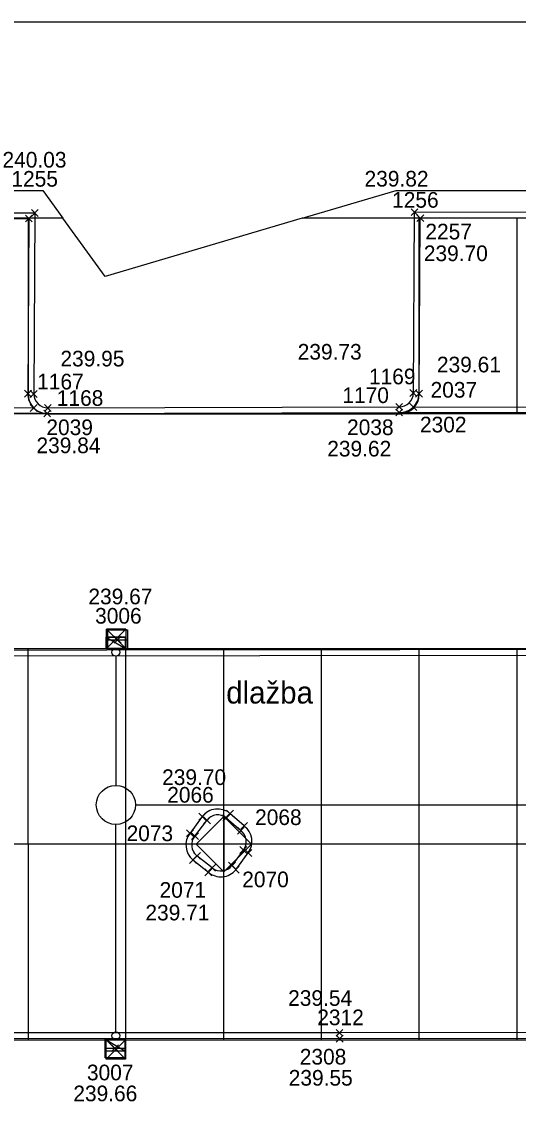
# Model space of a CAD drawing. Extents: x -264222 to -263676, y -1242344 to -1242060.
# Drawn here: x -264179.73 to -264167.04, y -1242214.48 to -1242186.47 of the extents above; entities that cross this region are included whole.
import ezdxf

# ---------------------------------------------------------------- set-up
doc = ezdxf.new("R2010")
doc.units = 0
for name, color, linetype in [('BODY_CISLO', 7, 'Continuous'), ('BODY_SYMBOL', 7, 'Continuous'), ('BODY_VYSKA', 7, 'Continuous'), ('BODY_VYSKY_UV', 7, 'Continuous'), ('KOORDINACNA_SITUACIA_DSP', 7, 'Continuous'), ('POPIS', 7, 'Continuous'), ('PROJEKT_DRS_OBRUBNIKY_KOMUNIKACIE', 7, 'Continuous'), ('PROJEKT_DRS_TDZ_VODOROVNE', 7, 'Continuous'), ('PROJEKT_DRS_UV_STAVBY', 7, 'Continuous'), ('RAM_NA_TLAC_8xA4_1-200', 7, 'Continuous'), ('SO_20-3_OBRUBNIKY_DOLNA_HRANA', 7, 'Continuous'), ('SO_20-3_OBRUBNIKY_HORNA_HRANA', 7, 'Continuous'), ('ULICNA_VPUST_POKLOP', 7, 'Continuous')]:
    doc.layers.add(name, color=color, linetype=linetype)

msp = doc.modelspace()

# ---------------------------------------------------------------- linework, layer by layer
at = {"layer": 'BODY_SYMBOL'}
for p, q in [((-264179.485, -1242191.437), (-264179.309, -1242191.261)), ((-264179.309, -1242191.437), (-264179.485, -1242191.261)), ((-264169.778, -1242191.417), (-264169.602, -1242191.241)), ((-264169.602, -1242191.417), (-264169.778, -1242191.241)), ((-264179.636, -1242191.579), (-264179.46, -1242191.403)), ((-264179.46, -1242191.579), (-264179.636, -1242191.403)), ((-264169.631, -1242191.57), (-264169.455, -1242191.394)), ((-264169.455, -1242191.57), (-264169.631, -1242191.394)), ((-264169.805, -1242196.035), (-264169.629, -1242195.859)), ((-264169.629, -1242196.035), (-264169.805, -1242195.859)), ((-264179.661, -1242196.053), (-264179.485, -1242195.877)), ((-264179.485, -1242196.053), (-264179.661, -1242195.877)), ((-264179.512, -1242196.06), (-264179.336, -1242195.884)), ((-264179.336, -1242196.06), (-264179.512, -1242195.884)), ((-264169.661, -1242196.056), (-264169.485, -1242195.88)), ((-264169.485, -1242196.056), (-264169.661, -1242195.88)), ((-264179.515, -1242196.418), (-264179.339, -1242196.242)), ((-264179.339, -1242196.418), (-264179.515, -1242196.242)), ((-264179.168, -1242196.562), (-264178.992, -1242196.386)), ((-264178.992, -1242196.562), (-264179.168, -1242196.386)), ((-264179.151, -1242196.418), (-264178.975, -1242196.242)), ((-264178.975, -1242196.418), (-264179.151, -1242196.242)), ((-264170.17, -1242196.537), (-264169.994, -1242196.361)), ((-264169.994, -1242196.537), (-264170.17, -1242196.361)), ((-264170.169, -1242196.391), (-264169.993, -1242196.215)), ((-264169.993, -1242196.391), (-264170.169, -1242196.215)), ((-264169.806, -1242196.394), (-264169.63, -1242196.218)), ((-264169.63, -1242196.394), (-264169.806, -1242196.218)), ((-264177.367, -1242202.343), (-264177.191, -1242202.167)), ((-264177.191, -1242202.343), (-264177.367, -1242202.167)), ((-264175.203, -1242206.862), (-264175.027, -1242206.686)), ((-264175.027, -1242206.862), (-264175.203, -1242206.686)), ((-264175.083, -1242206.958), (-264174.907, -1242206.782)), ((-264174.907, -1242206.958), (-264175.083, -1242206.782)), ((-264174.591, -1242206.894), (-264174.415, -1242206.718)), ((-264174.415, -1242206.894), (-264174.591, -1242206.718)), ((-264174.497, -1242206.783), (-264174.321, -1242206.607)), ((-264174.321, -1242206.783), (-264174.497, -1242206.607)), ((-264174.217, -1242207.22), (-264174.041, -1242207.044)), ((-264174.041, -1242207.22), (-264174.217, -1242207.044)), ((-264174.131, -1242207.098), (-264173.955, -1242206.922)), ((-264173.955, -1242207.098), (-264174.131, -1242206.922)), ((-264175.517, -1242207.287), (-264175.341, -1242207.111)), ((-264175.341, -1242207.287), (-264175.517, -1242207.111)), ((-264175.392, -1242207.362), (-264175.216, -1242207.186)), ((-264175.216, -1242207.362), (-264175.392, -1242207.186)), ((-264174.153, -1242207.716), (-264173.977, -1242207.54)), ((-264173.977, -1242207.716), (-264174.153, -1242207.54)), ((-264174.028, -1242207.791), (-264173.852, -1242207.615)), ((-264173.852, -1242207.791), (-264174.028, -1242207.615)), ((-264175.442, -1242207.971), (-264175.266, -1242207.795)), ((-264175.266, -1242207.971), (-264175.442, -1242207.795)), ((-264175.339, -1242207.865), (-264175.163, -1242207.689)), ((-264175.163, -1242207.865), (-264175.339, -1242207.689)), ((-264175.047, -1242208.286), (-264174.871, -1242208.11)), ((-264174.871, -1242208.286), (-264175.047, -1242208.11)), ((-264174.952, -1242208.173), (-264174.776, -1242207.997)), ((-264174.776, -1242208.173), (-264174.952, -1242207.997)), ((-264174.446, -1242208.112), (-264174.27, -1242207.936)), ((-264174.27, -1242208.112), (-264174.446, -1242207.936)), ((-264174.345, -1242208.221), (-264174.169, -1242208.045)), ((-264174.169, -1242208.221), (-264174.345, -1242208.045)), ((-264171.695, -1242212.388), (-264171.519, -1242212.212)), ((-264171.519, -1242212.388), (-264171.695, -1242212.212)), ((-264171.692, -1242212.535), (-264171.516, -1242212.359)), ((-264171.516, -1242212.535), (-264171.692, -1242212.359)), ((-264177.432, -1242212.781), (-264177.256, -1242212.605)), ((-264177.256, -1242212.781), (-264177.432, -1242212.605))]:
    msp.add_line(p, q, dxfattribs=at)
at = {"layer": 'KOORDINACNA_SITUACIA_DSP'}
for p, q in [((-264205.202, -1242190.775), (-264179.193, -1242190.775)), ((-264179.193, -1242190.775), (-264178.679, -1242191.482)), ((-264172.558, -1242191.482), (-264170.162, -1242190.775)), ((-264170.162, -1242190.775), (-264131.568, -1242190.775)), ((-264178.679, -1242191.482), (-264204.694, -1242191.482)), ((-264179.568, -1242191.482), (-264204.078, -1242191.482)), ((-264179.568, -1242191.482), (-264179.568, -1242195.982)), ((-264177.6, -1242192.97), (-264178.679, -1242191.482)), ((-264172.558, -1242191.482), (-264177.6, -1242192.97)), ((-264131.568, -1242191.482), (-264172.558, -1242191.482)), ((-264134.568, -1242191.482), (-264169.568, -1242191.482)), ((-264169.568, -1242195.982), (-264169.568, -1242191.482)), ((-264179.068, -1242196.482), (-264170.068, -1242196.482)), ((-264177.574, -1242202.186), (-264177.074, -1242202.186)), ((-264177.574, -1242202.476), (-264177.574, -1242202.186)), ((-264177.574, -1242202.186), (-264177.074, -1242202.476)), ((-264177.574, -1242202.186), (-264177.074, -1242202.476)), ((-264177.074, -1242202.186), (-264177.574, -1242202.186)), ((-264177.074, -1242202.186), (-264177.074, -1242202.476)), ((-264177.074, -1242202.476), (-264177.074, -1242202.186)), ((-264177.074, -1242202.476), (-264177.574, -1242202.476)), ((-264177.324, -1242202.676), (-264177.324, -1242205.976)), ((-264176.824, -1242206.476), (-264124.354, -1242206.476)), ((-264177.324, -1242212.276), (-264177.324, -1242206.976)), ((-264177.574, -1242212.476), (-264177.074, -1242212.476)), ((-264177.574, -1242212.766), (-264177.574, -1242212.476)), ((-264177.574, -1242212.476), (-264177.074, -1242212.766)), ((-264177.574, -1242212.476), (-264177.074, -1242212.766)), ((-264177.074, -1242212.476), (-264177.574, -1242212.476)), ((-264177.074, -1242212.476), (-264177.074, -1242212.766)), ((-264177.074, -1242212.766), (-264177.074, -1242212.476)), ((-264177.074, -1242212.766), (-264177.574, -1242212.766))]:
    msp.add_line(p, q, dxfattribs=at)
msp.add_lwpolyline([(-264173.861, -1242207.482), (-264174.568, -1242206.775), (-264175.275, -1242207.482), (-264174.568, -1242208.189)], close=True, dxfattribs=at)
for centre, radius in [((-264177.324, -1242202.576), 0.1), ((-264177.324, -1242206.476), 0.5), ((-264177.324, -1242212.376), 0.1)]:
    msp.add_circle(centre, radius, dxfattribs=at)
for centre, start, end in [((-264179.068, -1242195.982), 180, 270), ((-264170.068, -1242195.982), 270, 0)]:
    msp.add_arc(centre, 0.5, start, end, dxfattribs=at)
at = {"layer": 'PROJEKT_DRS_OBRUBNIKY_KOMUNIKACIE'}
for p, q in [((-264205.202, -1242190.775), (-264179.193, -1242190.775)), ((-264179.193, -1242190.775), (-264178.679, -1242191.482)), ((-264172.558, -1242191.482), (-264170.162, -1242190.775)), ((-264170.162, -1242190.775), (-264131.568, -1242190.775)), ((-264178.679, -1242191.482), (-264204.694, -1242191.482)), ((-264179.568, -1242191.482), (-264204.078, -1242191.482)), ((-264179.568, -1242191.482), (-264179.568, -1242195.982)), ((-264177.6, -1242192.97), (-264178.679, -1242191.482)), ((-264172.558, -1242191.482), (-264177.6, -1242192.97)), ((-264131.568, -1242191.482), (-264172.558, -1242191.482)), ((-264134.568, -1242191.482), (-264169.568, -1242191.482)), ((-264169.568, -1242195.982), (-264169.568, -1242191.482)), ((-264179.068, -1242196.482), (-264200.482, -1242196.482)), ((-264179.068, -1242196.482), (-264170.068, -1242196.482)), ((-264134.568, -1242196.482), (-264170.068, -1242196.482)), ((-264184.568, -1242202.482), (-264134.568, -1242202.482)), ((-264174.568, -1242206.775), (-264175.275, -1242207.482)), ((-264173.861, -1242207.482), (-264174.568, -1242206.775)), ((-264174.568, -1242206.775), (-264174.568, -1242208.189)), ((-264174.568, -1242208.189), (-264174.568, -1242206.775)), ((-264175.275, -1242207.482), (-264174.568, -1242208.189)), ((-264174.568, -1242208.189), (-264173.861, -1242207.482)), ((-264182.068, -1242212.482), (-264134.568, -1242212.482))]:
    msp.add_line(p, q, dxfattribs=at)
for centre, start, end in [((-264179.068, -1242195.982), 180, 270), ((-264170.068, -1242195.982), 270, 0)]:
    msp.add_arc(centre, 0.5, start, end, dxfattribs=at)
at = {"layer": 'PROJEKT_DRS_TDZ_VODOROVNE'}
for p, q in [((-264167.068, -1242196.482), (-264167.068, -1242191.482)), ((-264179.568, -1242207.482), (-264179.568, -1242202.482)), ((-264177.068, -1242207.482), (-264177.068, -1242202.482)), ((-264174.568, -1242207.482), (-264174.568, -1242202.482)), ((-264172.068, -1242207.482), (-264172.068, -1242202.482)), ((-264169.568, -1242207.482), (-264169.568, -1242202.482)), ((-264167.068, -1242207.482), (-264167.068, -1242202.482)), ((-264134.568, -1242207.482), (-264184.568, -1242207.482)), ((-264179.568, -1242207.482), (-264179.568, -1242212.482)), ((-264177.068, -1242212.482), (-264177.068, -1242207.482)), ((-264134.568, -1242207.482), (-264175.568, -1242207.482)), ((-264174.568, -1242212.482), (-264174.568, -1242207.482)), ((-264172.068, -1242212.482), (-264172.068, -1242207.482)), ((-264169.568, -1242212.482), (-264169.568, -1242207.482)), ((-264167.068, -1242212.482), (-264167.068, -1242207.482))]:
    msp.add_line(p, q, dxfattribs=at)
at = {"layer": 'PROJEKT_DRS_UV_STAVBY'}
for points in [[(-264177.568, -1242202.482), (-264177.568, -1242201.982), (-264177.068, -1242201.982), (-264177.068, -1242202.482), (-264177.568, -1242202.482), (-264177.068, -1242201.982), (-264177.568, -1242201.982), (-264177.068, -1242202.482)], [(-264177.574, -1242212.976), (-264177.574, -1242212.476), (-264177.074, -1242212.476), (-264177.074, -1242212.976), (-264177.574, -1242212.976), (-264177.074, -1242212.476), (-264177.574, -1242212.476), (-264177.074, -1242212.976)]]:
    msp.add_lwpolyline(points, dxfattribs=at)
at = {"layer": 'RAM_NA_TLAC_8xA4_1-200'}
msp.add_lwpolyline([(-264222.03, -1242186.466), (-264054.03, -1242186.466), (-264054.03, -1242305.266), (-264222.03, -1242305.266)], close=True, dxfattribs=at)
at = {"layer": 'SO_20-3_OBRUBNIKY_DOLNA_HRANA'}
for p, q in [((-264179.08, -1242196.474), (-264170.082, -1242196.449)), ((-264175.115, -1242206.774), (-264175.429, -1242207.199)), ((-264174.043, -1242207.01), (-264174.409, -1242206.695)), ((-264175.354, -1242207.883), (-264174.959, -1242208.198)), ((-264174.257, -1242208.133), (-264173.94, -1242207.703))]:
    msp.add_line(p, q, dxfattribs=at)
for points in [[(-264195.401, -1242191.504), (-264204.022, -1242191.531), (-264200.581, -1242196.322), (-264179.427, -1242196.33)], [(-264183.732, -1242191.496), (-264179.548, -1242191.491), (-264179.573, -1242195.965)], [(-264169.573, -1242195.968), (-264169.543, -1242191.482), (-264165.392, -1242191.472)], [(-264134.111, -1242196.42), (-264146.541, -1242196.439), (-264159.053, -1242196.46), (-264170.082, -1242196.449)], [(-264169.718, -1242196.306), (-264159.062, -1242196.316), (-264146.532, -1242196.293), (-264134.448, -1242196.268)], [(-264179.08, -1242196.474), (-264200.47, -1242196.472), (-264195.765, -1242203.023), (-264189.923, -1242211.168), (-264184.11, -1242219.268), (-264178.281, -1242227.391), (-264171.252, -1242237.149), (-264164.83, -1242246.079), (-264158.406, -1242254.997), (-264151.981, -1242263.929), (-264145.549, -1242272.885), (-264139.496, -1242281.305), (-264132.148, -1242291.541), (-264125.165, -1242301.265), (-264124.808, -1242301.762)], [(-264134.11, -1242202.476), (-264147.578, -1242202.485), (-264162.578, -1242202.5), (-264185.058, -1242202.528)], [(-264184.725, -1242202.666), (-264162.575, -1242202.645), (-264147.576, -1242202.628), (-264134.442, -1242202.625)], [(-264182.566, -1242212.438), (-264171.604, -1242212.447), (-264152.604, -1242212.425), (-264134.055, -1242212.391)], [(-264134.418, -1242212.255), (-264152.594, -1242212.281), (-264171.607, -1242212.3), (-264182.247, -1242212.302)]]:
    msp.add_lwpolyline(points, dxfattribs=at)
msp.add_arc((-264175.039, -1242207.502), 0.494, 142.0881, 230.4268, dxfattribs=at)
for centre, major_axis, ratio, start_param, end_param in [((-264179.078, -1242195.979), (0.429, -0.247), 0.999789, 3.637108, 5.231232), ((-264170.065, -1242195.957), (0.471, 0.143), 0.999489, 4.383995, 5.966844), ((-264174.724, -1242207.074), (-0.036, -0.492), 0.999308, 2.520309, 4.130532), ((-264174.351, -1242207.41), (0.421, 0.278), 0.999969, 5.080714, 6.615445), ((-264174.64, -1242207.818), (0.331, -0.369), 0.999844, 4.853682, 6.434325)]:
    msp.add_ellipse(centre, major_axis=major_axis, ratio=ratio, start_param=start_param, end_param=end_param, dxfattribs=at)
at = {"layer": 'SO_20-3_OBRUBNIKY_HORNA_HRANA'}
for p, q in [((-264183.873, -1242191.347), (-264179.397, -1242191.349)), ((-264179.397, -1242191.349), (-264179.424, -1242195.972)), ((-264169.717, -1242195.947), (-264169.69, -1242191.329)), ((-264169.69, -1242191.329), (-264165.241, -1242191.319)), ((-264179.063, -1242196.33), (-264170.081, -1242196.303)), ((-264175.304, -1242207.274), (-264174.995, -1242206.87)), ((-264174.503, -1242206.806), (-264174.129, -1242207.132)), ((-264174.065, -1242207.628), (-264174.358, -1242208.024)), ((-264174.864, -1242208.085), (-264175.251, -1242207.777))]:
    msp.add_line(p, q, dxfattribs=at)
for centre, major_axis, ratio, start_param, end_param in [((-264179.051, -1242195.957), (0.265, -0.263), 0.99953, 3.962801, 5.461977), ((-264170.082, -1242195.938), (0.363, 0.039), 0.999677, 4.60835, 6.149293), ((-264174.719, -1242207.074), (0.192, 0.285), 0.998416, 6.196667, 7.810173), ((-264175.038, -1242207.5), (0.007, -0.349), 0.999735, 3.989074, 5.60762), ((-264174.343, -1242207.412), (0.091, -0.341), 0.999551, 0.648448, 2.225311), ((-264174.641, -1242207.808), (0.349, -0.072), 0.999073, 4.239407, 5.834834)]:
    msp.add_ellipse(centre, major_axis=major_axis, ratio=ratio, start_param=start_param, end_param=end_param, dxfattribs=at)
at = {"layer": 'ULICNA_VPUST_POKLOP'}
for p, q in [((-264177.279, -1242202.255), (-264177.279, -1242202.255)), ((-264177.344, -1242212.693), (-264177.344, -1242212.693))]:
    msp.add_line(p, q, dxfattribs=at)
for points in [[(-264177.529, -1242202.255), (-264177.529, -1242202.005), (-264177.029, -1242202.005), (-264177.029, -1242202.505), (-264177.529, -1242202.505), (-264177.529, -1242202.255), (-264177.029, -1242202.255)], [(-264177.594, -1242212.693), (-264177.594, -1242212.443), (-264177.094, -1242212.443), (-264177.094, -1242212.943), (-264177.594, -1242212.943), (-264177.594, -1242212.693), (-264177.094, -1242212.693)]]:
    msp.add_lwpolyline(points, dxfattribs=at)

# ---------------------------------------------------------------- texts
at = {"layer": 'BODY_CISLO'}
for s, p in [('1255', (-264179.995, -1242190.676)), ('1256', (-264170.262, -1242191.214)), ('2257', (-264169.412, -1242192.024)), ('1167', (-264179.336, -1242195.857)), ('1169', (-264170.855, -1242195.727)), ('1168', (-264178.834, -1242196.278)), ('1170', (-264171.534, -1242196.206)), ('2037', (-264169.279, -1242196.068)), ('2039', (-264179.101, -1242197.026)), ('2038', (-264171.414, -1242197.025)), ('2302', (-264169.55, -1242196.956)), ('3006', (-264177.855, -1242201.843)), ('2066', (-264176.012, -1242206.418)), ('2068', (-264173.765, -1242206.99)), ('2073', (-264177.051, -1242207.401)), ('2070', (-264174.094, -1242208.58)), ('2071', (-264176.207, -1242208.848)), ('2312', (-264172.176, -1242212.105)), ('2308', (-264172.623, -1242213.111)), ('3007', (-264178.064, -1242213.514))]:
    msp.add_text(s, height=0.4, dxfattribs=at).set_placement(p)
at = {"layer": 'BODY_VYSKA'}
for s, p in [('240.03', (-264180.223, -1242190.189)), ('239.82', (-264170.967, -1242190.673)), ('239.70', (-264169.451, -1242192.579)), ('239.73', (-264172.676, -1242195.096)), ('239.95', (-264178.741, -1242195.27)), ('239.61', (-264169.117, -1242195.422)), ('239.84', (-264179.354, -1242197.487)), ('239.62', (-264171.921, -1242197.572)), ('239.70', (-264176.142, -1242205.967)), ('239.71', (-264176.569, -1242209.427)), ('239.54', (-264172.92, -1242211.611)), ('239.55', (-264172.905, -1242213.65))]:
    msp.add_text(s, height=0.4, dxfattribs=at).set_placement(p)
at = {"layer": 'BODY_VYSKY_UV'}
for s, p in [('239.67', (-264178.026, -1242201.349)), ('239.66', (-264178.412, -1242214.049))]:
    msp.add_text(s, height=0.4, dxfattribs=at).set_placement(p)
at = {"layer": 'POPIS'}
msp.add_text('dlažba', height=0.5625, rotation=360, dxfattribs=at).set_placement((-264174.503, -1242203.885))

doc.saveas('drawing.dxf')
